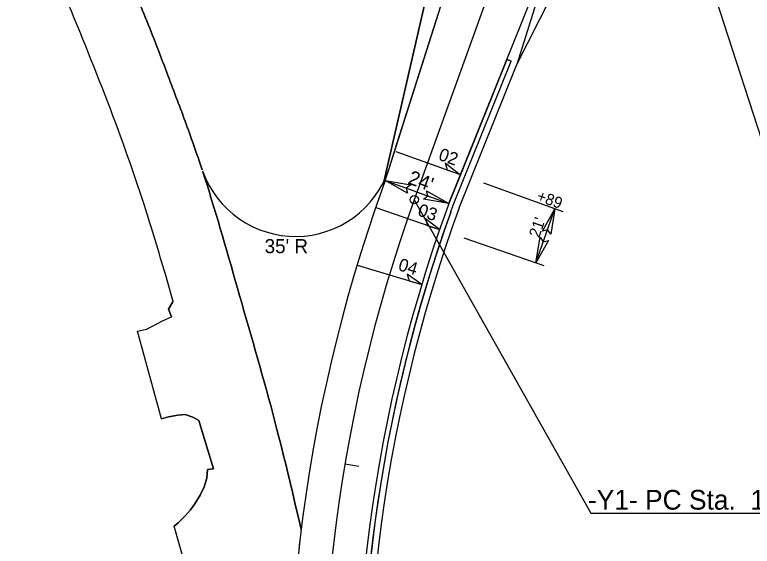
# Model space of a CAD drawing. Extents: x 1616561 to 1622460, y 896726 to 899651.
# Drawn here: x 1619318.1 to 1619580.2, y 897774.5 to 897963.2 of the extents above; entities that cross this region are included whole.
import ezdxf

# ---------------------------------------------------------------- set-up
doc = ezdxf.new("R2010")
doc.units = 0
for name, color, linetype in [('Old_Level_3', 7, 'Continuous'), ('Prop Conc Curb and Gutter', 7, 'Continuous'), ('Prop Dimension', 7, 'Continuous'), ('Prop Guardrail', 7, 'Continuous'), ('Prop Horizontal Alignment', 7, 'Continuous'), ('Prop Horizontal Alignment Tick Small', 7, 'Continuous'), ('Prop North Arrow NAD83 for Plan Sheets CELL', 7, 'Continuous'), ('Prop SBG', 7, 'Continuous'), ('Prop Shade Light', 7, 'Continuous'), ('Prop Superelevation  Arrow CELL', 7, 'Continuous'), ('Prop Terminator CELL', 7, 'Continuous'), ('Sheet Cutting Line CELL', 7, 'Continuous'), ('Sheet North Arrow CELL', 7, 'Continuous'), ('Sheet Sticker Preliminary CELL', 7, 'Continuous')]:
    doc.layers.add(name, color=color, linetype=linetype)

msp = doc.modelspace()

# ---------------------------------------------------------------- linework, layer by layer
at = {"layer": 'Old_Level_3'}
for q in [(1619451.1, 897908.57), (1619448.78, 897901.61)]:
    msp.add_line((1619449.75, 897904.32), q, dxfattribs=at)
msp.add_arc((1619977.61, 897711.39), 562, 160.2164, 186.4763, dxfattribs=at)
at = {"layer": 'Prop Conc Curb and Gutter'}
for p, q in [((1619374.23, 897861.76), (1619371.66, 897871.04)), ((1619370.23, 897819.76), (1619361.76, 897850.85)), ((1619388.74, 897801.91), (1619383.54, 897819.15)), ((1619379.38, 897765.46), (1619374.68, 897781.57))]:
    msp.add_line(p, q, dxfattribs=at)
for points in [[(1619373.79, 897855.94), (1619372.74, 897858.72), (1619374.25, 897861.27)], [(1619361.76, 897850.85), (1619364.89, 897851.54), (1619367.28, 897852.7), (1619370.61, 897854.48), (1619373.79, 897855.94)], [(1619383.54, 897819.15), (1619381.37, 897820.31), (1619378.65, 897821.23), (1619376.09, 897820.99), (1619372.76, 897820.43), (1619370.23, 897819.76)], [(1619374.68, 897781.57), (1619376.15, 897782.84), (1619378.82, 897785.36), (1619380.52, 897787.41), (1619382.05, 897789.55), (1619383.96, 897792.65), (1619385.42, 897795.61), (1619386.38, 897798.61), (1619386.56, 897801.73), (1619388.74, 897801.91)]]:
    msp.add_lwpolyline(points, dxfattribs=at)
msp.add_arc((1619977.61, 897711.39), 562, 172.9445, 177.5954, dxfattribs=at)
for points in [[(1619318.09, 898059), (1619336.73, 898023.03), (1619355.17, 897984.46), (1619359.66, 897974.11), (1619363.95, 897963.69), (1619368.1, 897953.21), (1619372.13, 897942.68), (1619375.39, 897934.08), (1619378.62, 897925.47), (1619384.71, 897908.13)], [(1619371.66, 897871.04), (1619364.15, 897895.46), (1619350.2, 897934.66), (1619334.15, 897974.32)], [(1619419.86, 897780.42), (1619411.27, 897815.95), (1619398.73, 897860.88), (1619386.3, 897903.15), (1619384.91, 897907.54)], [(1619384.91, 897907.54), (1619386.3, 897903.15), (1619398.73, 897860.88), (1619411.27, 897815.95), (1619419.86, 897780.42)]]:
    msp.add_spline(points, degree=3, dxfattribs=at)
at = {"layer": 'Prop Dimension'}
msp.add_line((1619449.75, 897904.32), (1619472.34, 897896.2), dxfattribs=at)
at = {"layer": 'Prop Guardrail'}
for p, q in [((1619496.51, 897945.53), (1619520.23, 897992.28)), ((1619476.05, 897894.71), (1619496.51, 897945.53))]:
    msp.add_line(p, q, dxfattribs=at)
msp.add_arc((1619977.61, 897711.41), 534, 159.9255, 186.4785, dxfattribs=at)
at = {"layer": 'Prop Horizontal Alignment'}
for p, q in [((1619449.19, 897903.92), (1619464.48, 897970.44)), ((1619473.88, 897895.58), (1619494.46, 897946.69)), ((1619492.92, 897947.31), (1619494.46, 897946.69)), ((1619472.93, 897892.92), (1619473.88, 897895.58))]:
    msp.add_line(p, q, dxfattribs=at)
msp.add_arc((1619977.61, 897711.39), 536.33, 160.2164, 184.2929, dxfattribs=at)
at = {"layer": 'Prop Horizontal Alignment Tick Small'}
msp.add_line((1619504.12, 897969.79), (1619496.51, 897945.53), dxfattribs=at)
at = {"layer": 'Prop North Arrow NAD83 for Plan Sheets CELL'}
for points in [[(1619476.06, 897906.55), (1619471.09, 897910.46), (1619471.71, 897908.12)], [(1619469.05, 897886.92), (1619464.03, 897890.77), (1619464.68, 897888.43)], [(1619462.72, 897867.38), (1619457.56, 897871.04), (1619458.29, 897868.72)]]:
    msp.add_lwpolyline(points, close=True, dxfattribs=at)
at = {"layer": 'Prop SBG'}
for p, q in [((1619473.88, 897895.58), (1619494.46, 897946.69)), ((1619472.93, 897892.92), (1619473.88, 897895.58))]:
    msp.add_line(p, q, dxfattribs=at)
msp.add_arc((1619977.61, 897711.39), 536.33, 160.1927, 184.2929, dxfattribs=at)
at = {"layer": 'Prop Shade Light'}
for p, q in [((1619464.48, 897970.44), (1619449.19, 897903.92)), ((1619473.88, 897895.58), (1619494.46, 897946.69)), ((1619494.46, 897946.69), (1619492.92, 897947.31)), ((1619492.92, 897947.31), (1619492.92, 897947.31)), ((1619472.34, 897896.2), (1619471.36, 897893.49)), ((1619472.93, 897892.92), (1619473.88, 897895.58))]:
    msp.add_line(p, q, dxfattribs=at)
for points in [[(1619451.1, 897908.57), (1619453.08, 897914.8), (1619474.01, 897980.62)], [(1619492.92, 897947.31), (1619476.44, 897906.4), (1619472.34, 897896.2)], [(1619449.19, 897903.92), (1619449.46, 897904.47), (1619449.77, 897905.14), (1619450.05, 897905.77), (1619450.2, 897906.14), (1619450.43, 897906.71), (1619450.62, 897907.2), (1619450.81, 897907.71), (1619451.1, 897908.57)]]:
    msp.add_lwpolyline(points, dxfattribs=at)
for radius in [538, 536.33]:
    msp.add_arc((1619977.61, 897711.39), radius, 160.2164, 186.4763, dxfattribs=at)
at = {"layer": 'Prop Superelevation  Arrow CELL'}
for p, q in [((1619461.05, 897900.26), (1619465.75, 897898.57)), ((1619435.42, 897803.74), (1619440.35, 897802.9))]:
    msp.add_line(p, q, dxfattribs=at)
at = {"layer": 'Prop Terminator CELL'}
for p, q in [((1619451.1, 897908.57), (1619474.01, 897980.62)), ((1619472.34, 897896.2), (1619502.24, 897970.46)), ((1619472.34, 897896.2), (1619471.36, 897893.49)), ((1619374.23, 897861.76), (1619371.66, 897871.04)), ((1619374.23, 897861.76), (1619374.25, 897861.27)), ((1619370.23, 897819.76), (1619361.76, 897850.85)), ((1619383.54, 897819.15), (1619388.74, 897801.91)), ((1619379.38, 897765.46), (1619374.68, 897781.57))]:
    msp.add_line(p, q, dxfattribs=at)
for points in [[(1619457.7, 897899.82), (1619449.75, 897904.32), (1619458.81, 897902.77), (1619457.19, 897901.65)], [(1619464.39, 897900.71), (1619472.34, 897896.2), (1619463.28, 897897.76), (1619464.9, 897898.87)], [(1619505.57, 897886.36), (1619510.02, 897894.34), (1619508.53, 897885.27), (1619507.4, 897886.88)], [(1619507.71, 897883.09), (1619503.26, 897875.12), (1619504.75, 897884.18), (1619505.88, 897882.57)]]:
    msp.add_lwpolyline(points, close=True, dxfattribs=at)
for points in [[(1619374.25, 897861.27), (1619372.74, 897858.72), (1619373.79, 897855.94)], [(1619361.76, 897850.85), (1619364.89, 897851.54), (1619367.28, 897852.7), (1619370.61, 897854.48), (1619373.79, 897855.94)], [(1619370.23, 897819.76), (1619372.76, 897820.43), (1619376.09, 897820.99), (1619378.65, 897821.23), (1619381.37, 897820.31), (1619383.54, 897819.15)], [(1619388.74, 897801.91), (1619386.56, 897801.73), (1619386.38, 897798.61), (1619385.42, 897795.61), (1619383.96, 897792.65), (1619382.05, 897789.55), (1619380.52, 897787.41), (1619378.82, 897785.36), (1619376.15, 897782.84), (1619374.68, 897781.57)]]:
    msp.add_lwpolyline(points, dxfattribs=at)
for centre, radius, start, end in [((1619417.84, 897919.51), 35.02, 199.4937, 341.7967), ((1619977.61, 897711.39), 538, 160.2164, 186.4763)]:
    msp.add_arc(centre, radius, start, end, dxfattribs=at)
for points in [[(1619384.71, 897908.13), (1619378.62, 897925.47), (1619375.39, 897934.08), (1619372.13, 897942.68), (1619368.1, 897953.21), (1619363.95, 897963.69), (1619359.66, 897974.11), (1619355.17, 897984.46), (1619336.73, 898023.03), (1619318.09, 898059)], [(1619371.66, 897871.04), (1619364.15, 897895.46), (1619350.2, 897934.66), (1619334.15, 897974.32)]]:
    msp.add_spline(points, degree=3, dxfattribs=at)
at = {"layer": 'Sheet Cutting Line CELL'}
msp.add_line((1619528.74, 898088.46), (1619460.07, 897897.55), dxfattribs=at)
msp.add_arc((1619977.61, 897711.39), 550, 160.2164, 186.4763, dxfattribs=at)
at = {"layer": 'Sheet North Arrow CELL'}
for p, q in [((1619528.74, 898088.46), (1619598.19, 897873.05)), ((1619460.07, 897897.55), (1619522.84, 897786.18)), ((1619522.84, 897786.18), (1619629.95, 897786.18))]:
    msp.add_line(p, q, dxfattribs=at)
msp.add_circle((1619460.07, 897897.55), 1.5, dxfattribs=at)
at = {"layer": 'Sheet Sticker Preliminary CELL'}
for p, q in [((1619453.48, 897914.68), (1619476.06, 897906.55)), ((1619484.6, 897903.48), (1619512.84, 897893.32)), ((1619446.36, 897894.75), (1619469.05, 897886.92)), ((1619503.26, 897875.12), (1619510.02, 897894.34)), ((1619477.65, 897883.95), (1619506.09, 897874.14)), ((1619439.75, 897874.34), (1619462.72, 897867.38))]:
    msp.add_line(p, q, dxfattribs=at)

# ---------------------------------------------------------------- texts
at = {"layer": 'Prop Dimension'}
for s, height, rotation, p in [("24'", 5.044, 340.2164, (1619457.5, 897903.34)), ("35' R", 5, 0.0004, (1619406.89, 897878.55))]:
    msp.add_text(s, height=height, rotation=rotation, dxfattribs=at).set_placement(p)
at = {"layer": 'Sheet North Arrow CELL'}
msp.add_text('-Y1- PC Sta.  12+02.88', height=7, rotation=360, dxfattribs=at).set_placement((1619521.78, 897787.47))
at = {"layer": 'Sheet Sticker Preliminary CELL'}
for s, height, rotation, p in [('02', 4.5, 340.2164, (1619468.33, 897911.82)), ('+89', 4, 340.2442, (1619503.28, 897897.29)), ('03', 4.5, 340.8836, (1619460.95, 897892.04)), ("21'", 4, 70.6096, (1619504.43, 897883.79)), ('04', 4.5, 343.0712, (1619454.04, 897872.59))]:
    msp.add_text(s, height=height, rotation=rotation, dxfattribs=at).set_placement(p)

doc.saveas('drawing.dxf')
